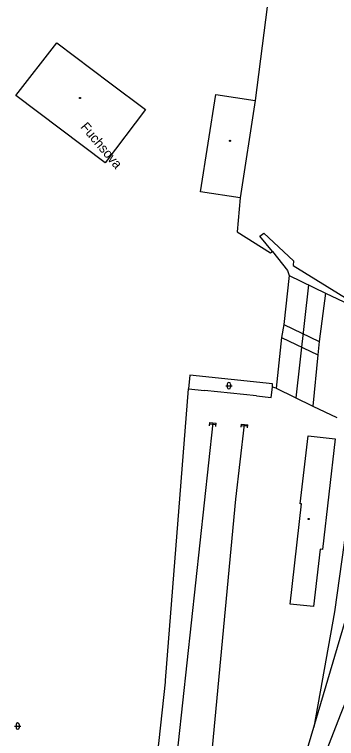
# Model space of a CAD drawing. Extents: x -598932 to -598196, y -1162207 to -1161504.
# Drawn here: x -598346.4 to -598296.1, y -1161816.9 to -1161703.7 of the extents above; entities that cross this region are included whole.
import ezdxf

# ---------------------------------------------------------------- set-up
doc = ezdxf.new("R2010")
doc.units = 0
for name, color, linetype in [('DOP - kresba z DSPS bez soueadnic', 7, 'Continuous'), ('DOP - kresba z DSPS bez souradnic - shora neviditelna', 7, 'Continuous'), ('DOP - rozhrani ploch obecne', 7, 'Continuous'), ('Level 12', 7, 'Continuous'), ('Level 36', 7, 'Continuous'), ('Level 39', 7, 'Continuous'), ('TM - budovy zdene_ betonove - VP', 7, 'Continuous'), ('TM - CD - osa koleji', 7, 'Continuous'), ('TM - letecke snimky - pomocna linie', 7, 'Continuous'), ('ulice', 7, 'Continuous')]:
    doc.layers.add(name, color=color, linetype=linetype)

msp = doc.modelspace()

# ---------------------------------------------------------------- linework, layer by layer
at = {"layer": 'DOP - kresba z DSPS bez soueadnic'}
for points in [[(-598305.85, -1161693.93), (-598308.81, -1161717.15)], [(-598311.17, -1161732.4), (-598311.63, -1161737.69)], [(-598311.63, -1161737.69), (-598306.43, -1161740.96)], [(-598308.07, -1161738.36), (-598307.47, -1161737.89)], [(-598307.47, -1161737.89), (-598302.81, -1161742.23)], [(-598306.13, -1161740.78), (-598308.07, -1161738.36)], [(-598306.43, -1161740.96), (-598306.13, -1161740.78)], [(-598306.13, -1161740.78), (-598303.77, -1161743.74)], [(-598302.81, -1161742.23), (-598302.87, -1161742.97)], [(-598303.77, -1161743.74), (-598303.51, -1161744.5)], [(-598302.87, -1161742.97), (-598294.03, -1161748.44)], [(-598303.51, -1161744.5), (-598304.31, -1161752.19)], [(-598297.83, -1161747.26), (-598298.8, -1161754.87)], [(-598304.31, -1161752.19), (-598304.72, -1161754.21)], [(-598304.72, -1161754.21), (-598305.52, -1161762.14)], [(-598298.8, -1161754.87), (-598299.04, -1161756.95)], [(-598299.04, -1161756.95), (-598299.79, -1161764.96)], [(-598305.52, -1161762.14), (-598306.09, -1161761.99)]]:
    msp.add_lwpolyline(points, dxfattribs=at)
at = {"layer": 'DOP - kresba z DSPS bez souradnic - shora neviditelna'}
for points in [[(-598303.51, -1161744.5), (-598297.83, -1161747.26)], [(-598297.83, -1161747.26), (-598294.04, -1161749.08)], [(-598304.31, -1161752.19), (-598298.8, -1161754.87)], [(-598304.72, -1161754.21), (-598299.04, -1161756.95)], [(-598305.52, -1161762.14), (-598299.79, -1161764.96)], [(-598299.79, -1161764.96), (-598296.04, -1161766.73)]]:
    msp.add_lwpolyline(points, dxfattribs=at)
at = {"layer": 'DOP - rozhrani ploch obecne'}
for points in [[(-598319.01, -1161760.13), (-598319.23, -1161762.27)], [(-598306.11, -1161761.48), (-598319.01, -1161760.13)], [(-598306.31, -1161763.6), (-598306.09, -1161761.99)], [(-598306.09, -1161761.99), (-598306.11, -1161761.48)], [(-598319.23, -1161762.27), (-598316.73, -1161762.53)], [(-598308.63, -1161763.36), (-598316.73, -1161762.53)], [(-598308.63, -1161763.36), (-598306.31, -1161763.6)]]:
    msp.add_lwpolyline(points, dxfattribs=at)
at = {"layer": 'Level 12'}
for p, q in [((-598315.96, -1161768.02), (-598315.91, -1161767.53)), ((-598315.91, -1161767.53), (-598314.91, -1161767.63)), ((-598314.97, -1161768.13), (-598314.91, -1161767.63)), ((-598314.94, -1161767.88), (-598315.93, -1161767.78)), ((-598311.02, -1161768.26), (-598310.97, -1161767.76)), ((-598310, -1161768.11), (-598310.99, -1161768.01)), ((-598310.97, -1161767.76), (-598309.97, -1161767.86)), ((-598310.02, -1161768.36), (-598309.97, -1161767.86))]:
    msp.add_line(p, q, dxfattribs=at)
at = {"layer": 'Level 36'}
for p, q in [((-598313.42, -1161761.76), (-598312.42, -1161761.76)), ((-598313.17, -1161761.51), (-598313.17, -1161762.01)), ((-598312.67, -1161761.51), (-598312.67, -1161762.01)), ((-598346.45, -1161814.99), (-598345.45, -1161814.99)), ((-598346.2, -1161814.74), (-598346.2, -1161815.24)), ((-598345.7, -1161814.74), (-598345.7, -1161815.24))]:
    msp.add_line(p, q, dxfattribs=at)
for centre, start, end in [((-598312.92, -1161761.51), 0, 180), ((-598312.92, -1161762.01), 180, 0), ((-598345.95, -1161814.74), 0, 180), ((-598345.95, -1161815.24), 180, 0)]:
    msp.add_arc(centre, 0.25, start, end, dxfattribs=at)
at = {"layer": 'Level 39'}
for centre, radius in [((-598336.2, -1161716.77), 0.09), ((-598336.2, -1161716.77), 0.0398), ((-598312.74, -1161723.46), 0.09), ((-598312.74, -1161723.46), 0.0398), ((-598300.45, -1161782.6), 0.09), ((-598300.45, -1161782.6), 0.0398)]:
    msp.add_circle(centre, radius, dxfattribs=at)
at = {"layer": 'TM - budovy zdene_ betonove - VP'}
for points in [[(-598346.25, -1161716.39), (-598339.84, -1161708.16)], [(-598339.84, -1161708.16), (-598331.52, -1161714.39)], [(-598331.52, -1161714.39), (-598325.95, -1161718.56)], [(-598332.27, -1161726.89), (-598346.25, -1161716.39)], [(-598317.35, -1161731.43), (-598314.98, -1161716.23)], [(-598314.98, -1161716.23), (-598308.81, -1161717.15)], [(-598308.81, -1161717.15), (-598311.17, -1161732.4)], [(-598325.95, -1161718.56), (-598332.27, -1161726.89)], [(-598311.17, -1161732.4), (-598317.35, -1161731.43)], [(-598301.76, -1161780.21), (-598300.55, -1161769.58)], [(-598300.55, -1161769.58), (-598296.32, -1161770.06)], [(-598296.32, -1161770.06), (-598298.27, -1161787.35)], [(-598301.56, -1161780.24), (-598301.76, -1161780.21)], [(-598303.32, -1161795.9), (-598301.56, -1161780.24)], [(-598298.67, -1161787.31), (-598299.67, -1161796.29)], [(-598298.27, -1161787.35), (-598298.67, -1161787.31)], [(-598299.67, -1161796.29), (-598303.32, -1161795.9)]]:
    msp.add_lwpolyline(points, dxfattribs=at)
at = {"layer": 'TM - CD - osa koleji'}
for points in [[(-598300.45, -1161745.99), (-598302.44, -1161763.65)], [(-598315.41, -1161767.58), (-598320.86, -1161817.58), (-598324.9, -1161852.77), (-598325.79, -1161864.77), (-598326.17, -1161880.48)], [(-598318.45, -1161844.78), (-598315.78, -1161821.69), (-598311.86, -1161779.52), (-598310.47, -1161767.81)], [(-598292.87, -1161768.29), (-598293.22, -1161771.98), (-598294.88, -1161786.35), (-598296.39, -1161797.1), (-598299.64, -1161815.15)], [(-598310.31, -1161852.18), (-598307.8, -1161843.38), (-598302.86, -1161826.04), (-598299.64, -1161815.15), (-598294.44, -1161797.56), (-598287.03, -1161771.17)], [(-598279.66, -1161774.81), (-598281.63, -1161778.87), (-598284.25, -1161785.34), (-598290.86, -1161801.71), (-598295.43, -1161813.02), (-598300.65, -1161826.42)]]:
    msp.add_lwpolyline(points, dxfattribs=at)
at = {"layer": 'TM - letecke snimky - pomocna linie'}
msp.add_lwpolyline([(-598345.39, -1161932), (-598345.23, -1161933.17), (-598341.9, -1161949.98), (-598339.75, -1161944.21), (-598339.66, -1161943.91), (-598337.49, -1161935.34), (-598337.46, -1161935.23), (-598334.67, -1161925.84), (-598334.58, -1161925.43), (-598332.32, -1161909.94), (-598332.3, -1161909.85), (-598330.27, -1161898.83), (-598330.22, -1161898.47), (-598329.83, -1161891.84), (-598329.69, -1161889.41), (-598329.17, -1161880.36), (-598328.79, -1161864.7), (-598328.78, -1161864.55), (-598327.89, -1161852.55), (-598327.88, -1161852.43), (-598323.84, -1161817.24), (-598322.85, -1161808.11), (-598322.82, -1161807.86), (-598319.23, -1161762.27)], dxfattribs=at)

# ---------------------------------------------------------------- texts
at = {"layer": 'ulice'}
msp.add_text('Fuchsova', height=1.5, rotation=310.241, dxfattribs=at).set_placement((-598336.22, -1161721.34))

doc.saveas('drawing.dxf')
